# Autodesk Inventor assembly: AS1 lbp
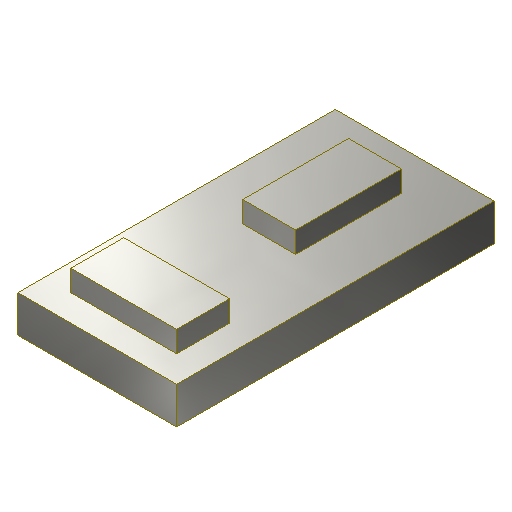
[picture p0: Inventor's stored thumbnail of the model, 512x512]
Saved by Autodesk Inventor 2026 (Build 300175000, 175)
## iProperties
Created: 2022-01
Part Number: AS1 lbp
Document SubType Name: Assembly
Designer: Lars Bertram Pedersen
Author: Lars Bertram Pedersen
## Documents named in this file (3)
- C:\INV GR\INV GR Assembly\AS1.iam
- C:\INV GR\INV GR Part\iv1-ma02.ipt
- C:\INV GR\INV GR Part\iv1-ma01.ipt
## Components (3 placed, 2 different names)
1. iv1-ma02:1 — Mate:1, Mate:2, Mate:3, Mate:4, Mate:5, Mate:6
2. iv1-ma01:1 — Mate:1, Mate:2, Mate:3
3. iv1-ma01:2 — Mate:4, Mate:5, Mate:6
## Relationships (6: Mate 6)
- Mate:1: iv1-ma02:1 ↔ iv1-ma01:1
- Mate:2: iv1-ma02:1 ↔ iv1-ma01:1
- Mate:3: iv1-ma02:1 ↔ iv1-ma01:1
- Mate:4: iv1-ma02:1 ↔ iv1-ma01:2
- Mate:5: iv1-ma02:1 ↔ iv1-ma01:2
- Mate:6: iv1-ma02:1 ↔ iv1-ma01:2
